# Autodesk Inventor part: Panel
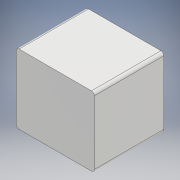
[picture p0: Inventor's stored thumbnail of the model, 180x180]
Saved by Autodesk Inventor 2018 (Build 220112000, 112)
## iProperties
Created: 2022-01
Part Number: Panel
Material: Plástico, blanco opaco
Document SubType Name: Modeling
Designer: Asus
Density: 0.952 g/cm^3
Appearance: Suave - Blanco
Author: Asus
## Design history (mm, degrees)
sketch "Boceto1"
  geometry: L1 (135, 120)-(-135, 120); L2 (-135, 120)-(-135, -120); L3 (-135, -120)-(135, -120); L4 (135, -120)-(135, 120); L5 (135, 120)-(-135, -120); L6 (-135, 120)-(135, -120); 1 further point
  constraints: 12 end point, 2 midpoint, 2 parallel, 1 horizontal, 1 perpendicular
  dimensions: "d0" = 270 distance of L3.end L2.end; "d1" = 240 distance of L2.end L1.end
extrude "Extrusión1" new body sketch "Boceto1" distance "d2" = 240; taper "d3" = 0 deg
fillet "Empalme4" dims "d14" = 10
node "Sólido1"
